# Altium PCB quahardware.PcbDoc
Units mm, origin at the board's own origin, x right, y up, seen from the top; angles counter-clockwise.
Board outline 80 x 75 mm, 2 copper layers (Top Layer, Bottom Layer); 57 components, 46 nets, 248 pads, 42 vias.
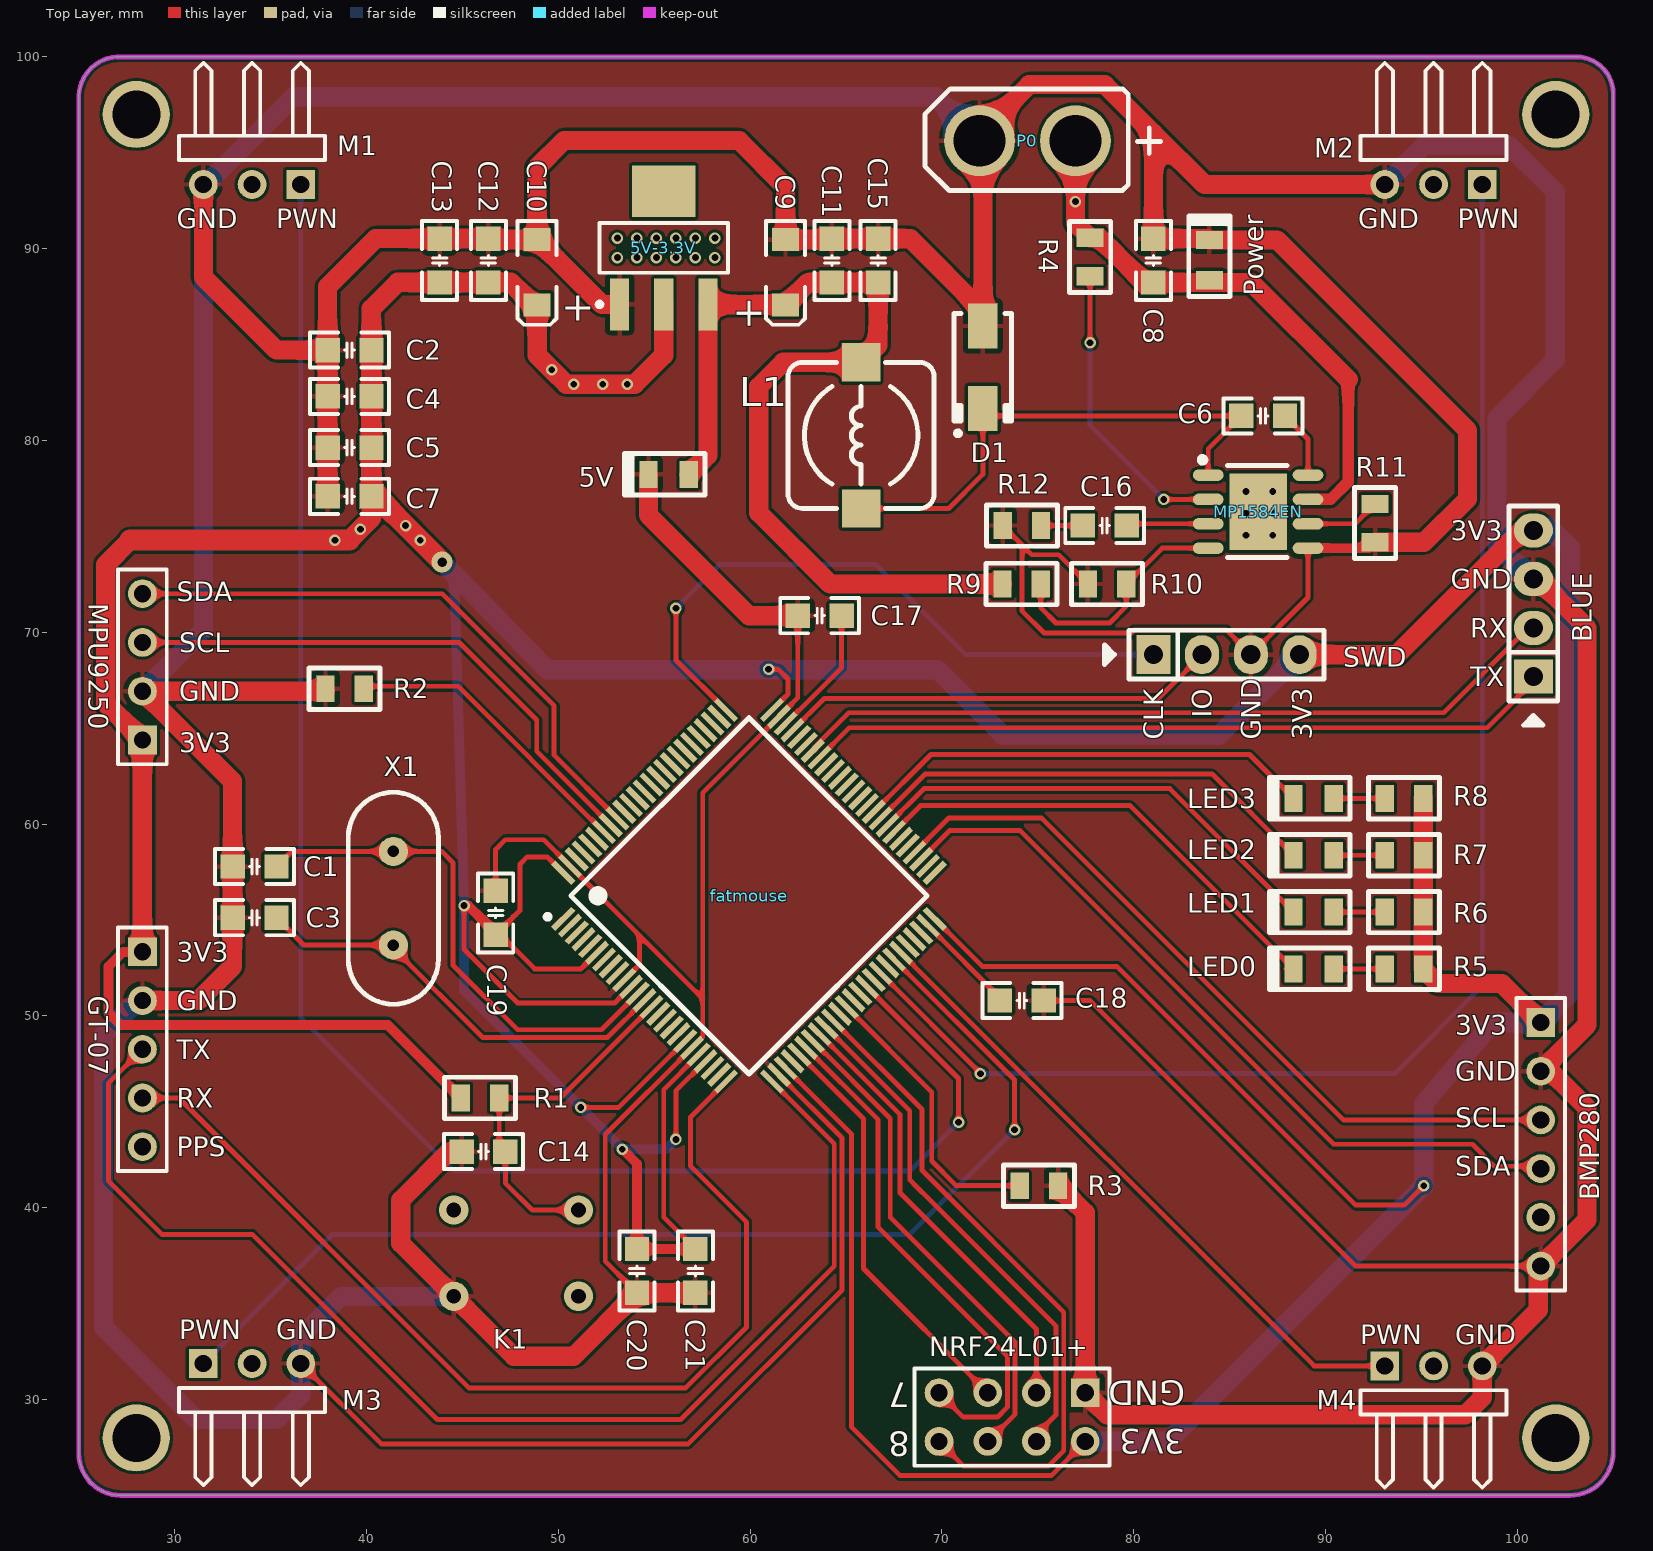
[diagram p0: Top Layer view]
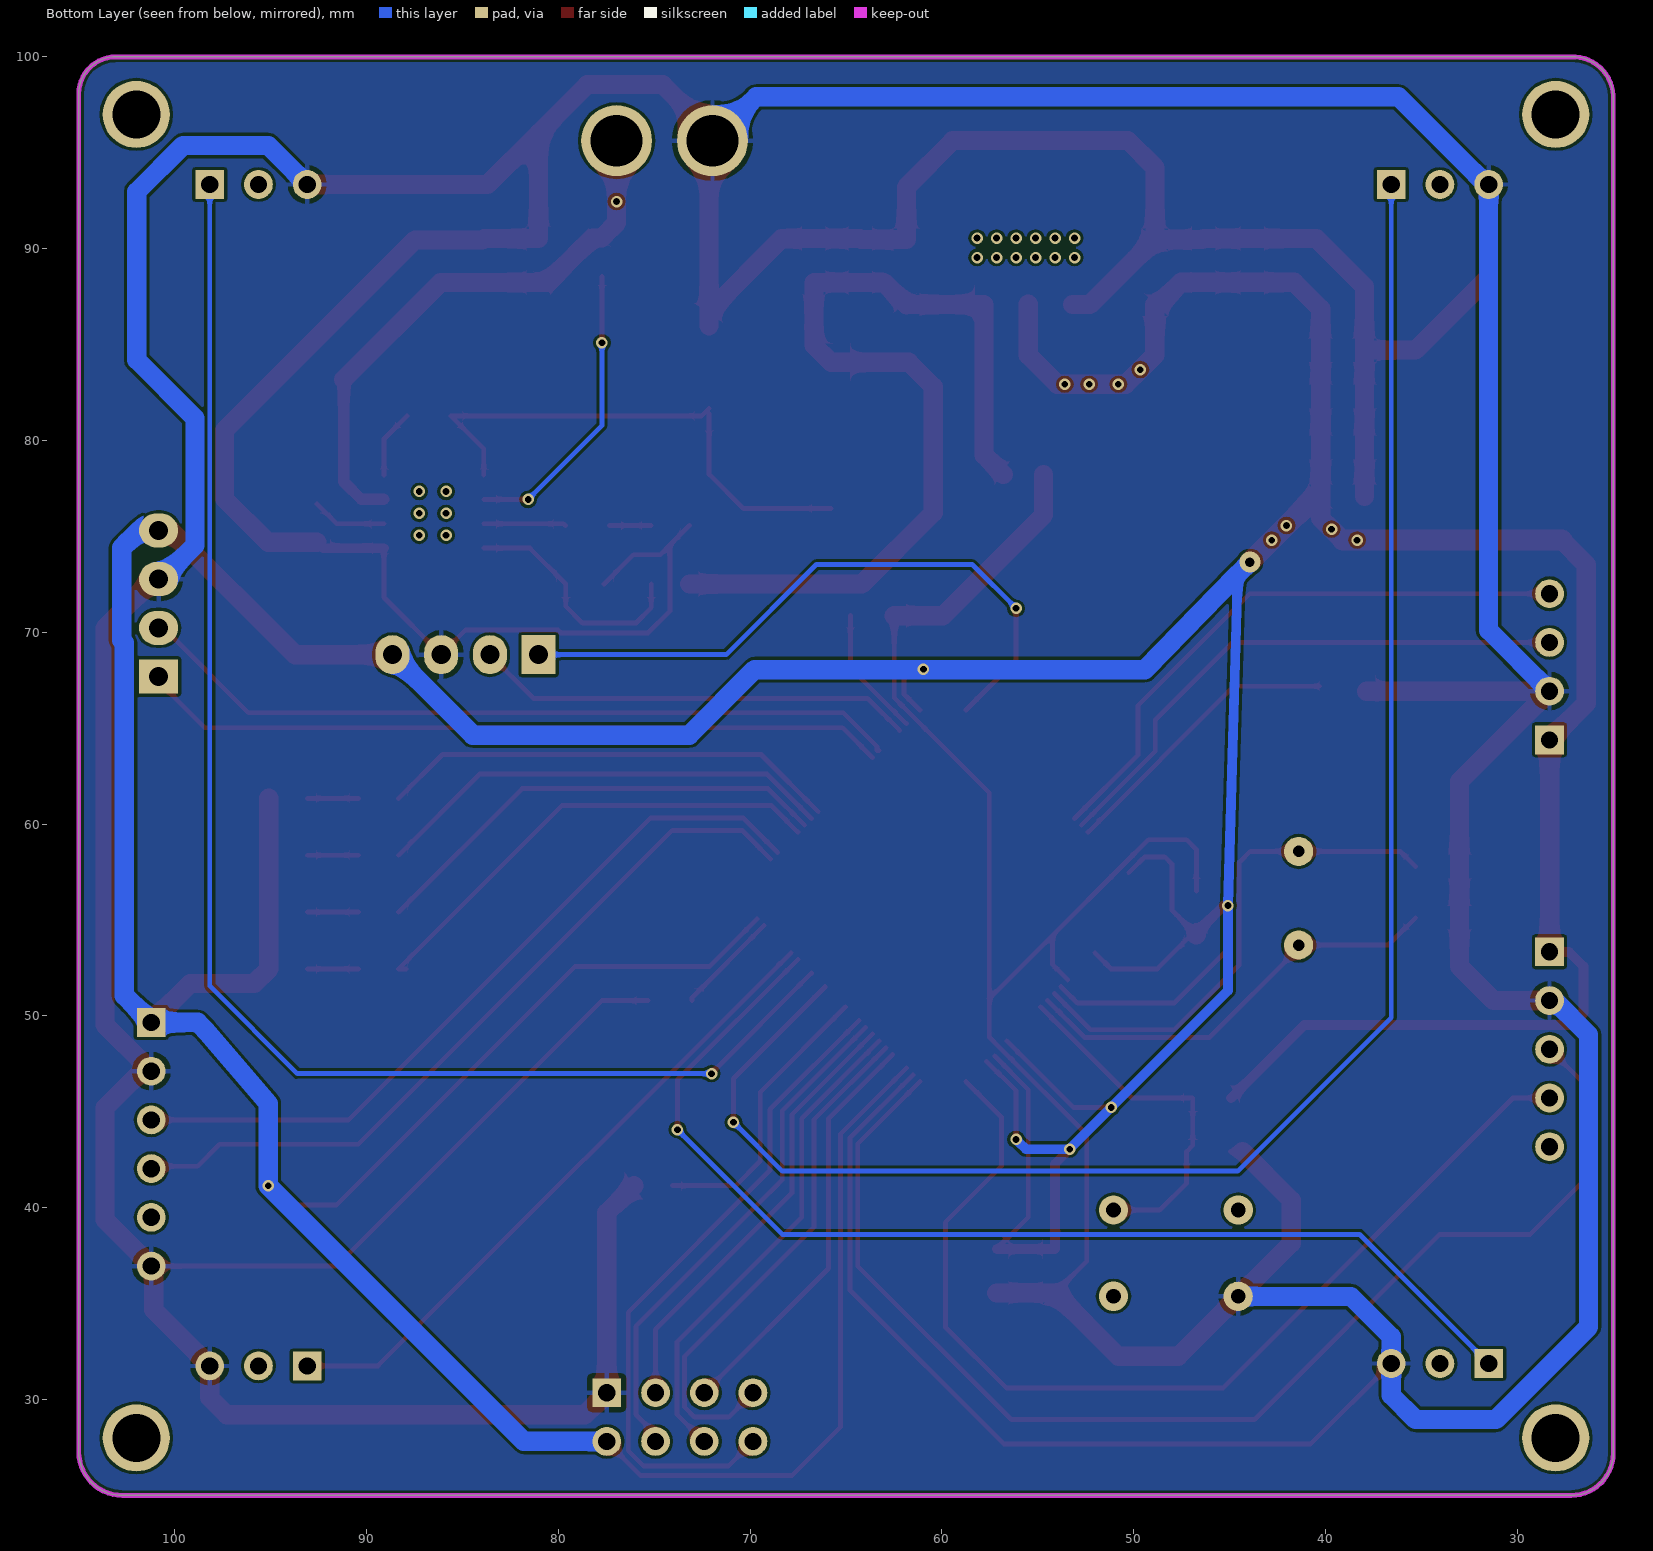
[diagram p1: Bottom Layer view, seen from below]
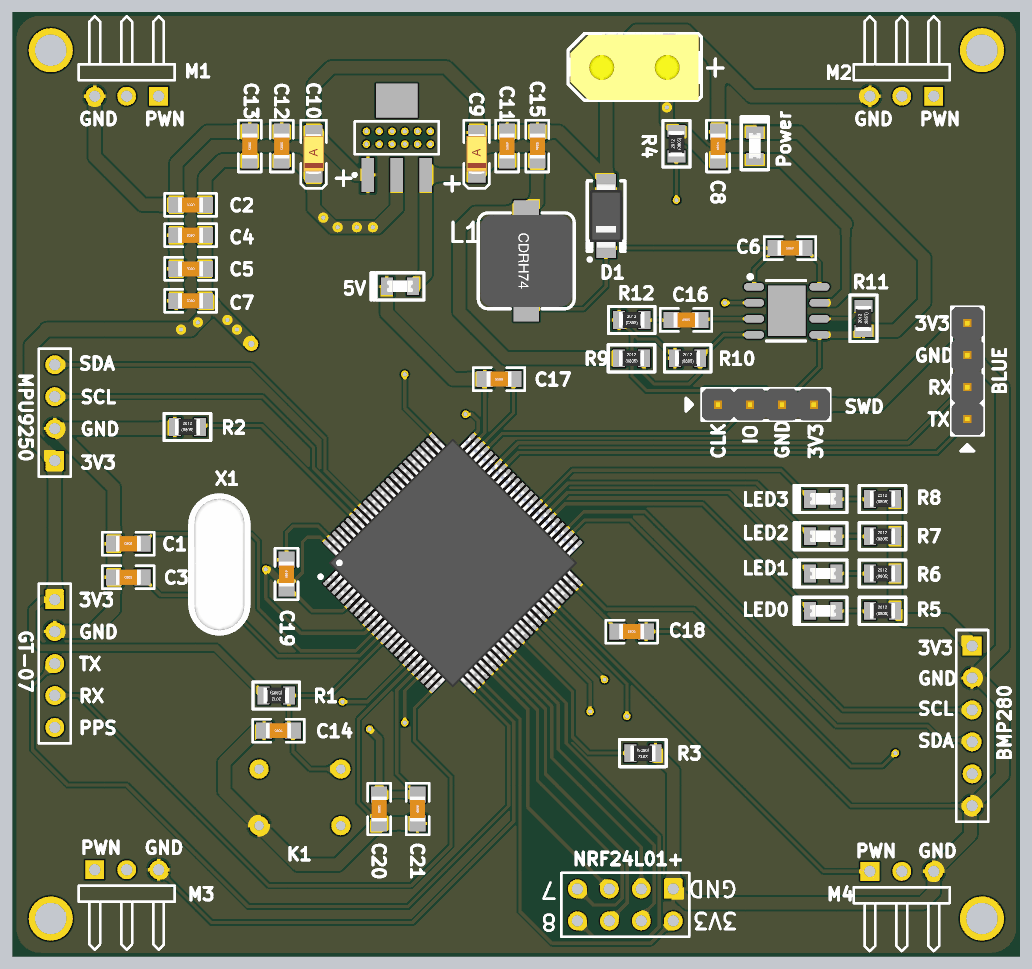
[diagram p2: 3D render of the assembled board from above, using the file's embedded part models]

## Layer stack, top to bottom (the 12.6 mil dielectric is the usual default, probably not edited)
Top Solder: solder mask 0.0102, Solder Resist, Dk 3.5
Top Layer: signal copper 0.0356
Dielectric 1: dielectric 0.32, FR-4, Dk 4.8
Bottom Layer: signal copper 0.0356
Bottom Solder: solder mask 0.0102, Solder Resist, Dk 3.5

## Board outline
25,27.197 25,97.981 cw(c27.126,97.882) 26.975,100.004 26.975,100 103.073,100 cw(c103.073,98.073) 105,98.073 105,27.276 cw(c102.724,27.276) 102.724,25 27.197,25 cw(c27.197,27.197)

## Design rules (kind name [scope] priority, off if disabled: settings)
Clearance [All] p1: gap=0.147 ignorepadtopadclearanceinfootprint=FALSE
PolygonConnect [All] p1: connectstyle=Relief reliefconductorwidth=0.254 reliefentries=4 polygonreliefangle="90 Angle" airgapwidth=0.254
RoutingVias [All] p1: holewidth=0.711 width=1.27 viastyle="Through Hole" minholewidth=0.711 minwidth=1.27 maxholewidth=0.711 maxwidth=1.27
SolderMaskExpansion [All] p1: expansion=0.102
Width [InNet('3.3V')] p1: maxlimit=2.54 minlimit=0.254 preferedwidth=1.016
30 further rules are at their usual default settings.

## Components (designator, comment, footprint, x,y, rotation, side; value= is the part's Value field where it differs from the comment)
5V "BLUE" LED-0805 55.753,78.232 r180 top (schematic designator LED6)
5V-3.3V "LM1117-3.3" SOT223_M 55.499,90.043 r90 top
BLUE "Header 4" PIN-4-2.54-1.0 100.838,71.501 r90 top
BMP280 "Header 6" HDR1X6 101.219,49.657 r270 top
C1 "Cap" "C 0805" 34.163,57.785 r0 top value=22pF
C2 "Cap" "C 0805" 39.116,84.709 r180 top value=100pF
C3 "Cap" "C 0805" 34.163,55.118 r0 top value=22pF
C4 "Cap" "C 0805" 39.116,82.296 r180 top value=100pF
C5 "Cap" "C 0805" 39.116,79.629 r180 top value=100pF
C6 "Cap" "C 0805" 86.741,81.28 r180 top value=100nF
C7 "Cap" "C 0805" 39.116,77.089 r180 top value=100pF
C8 "Cap" "C 0805" 81.026,89.381 r90 top value=10uF
C9 "10uF" "CD A(3216)" 61.849,88.773 r90 top
C10 "10uF" "CD A(3216)" 48.895,88.773 r90 top
C11 "0.01uF" "C 0805" 64.262,89.381 r270 top
C12 "0.01uF" "C 0805" 46.355,89.381 r270 top
C13 "0.01uF" "C 0805" 43.815,89.381 r270 top
C14 "Cap" "C 0805" 46.101,42.926 r0 top value=100pF
C15 "Cap" "C 0805" 66.675,89.381 r90 top value=22uF
C16 "Cap" "C 0805" 78.486,75.565 r0 top value=150pF
C17 "Cap" "C 0805" 63.627,70.866 r180 top value=2.2uF
C18 "Cap" "C 0805" 74.168,50.8 r0 top value=2.2uF
C19 "Cap" "C 0805" 46.736,55.372 r90 top value=100nF
C20 "Cap" "C 0805" 54.102,36.703 r90 top value=1uF
C21 "Cap" "C 0805" 57.15,36.703 r90 top value=100nF
D1 "D Schottky" SMA 72.136,83.82 r270 top
fatmouse "STM32F407VET6" QFP-100-0.5 59.944,56.261 r45 top
GT-07 "Header 5" HDR1X5 28.321,53.34 r270 top
K1 "KEY_L" key 51.054,39.878 r180 top (schematic designator KEY1)
L1 "Inductor" CDRH74 65.786,80.264 r90 top value=4.7uH
LED0 "BLUE" LED-0805 89.374,52.451 r180 top
LED1 "BLUE" LED-0805 89.374,55.414 r180 top
LED2 "BLUE" LED-0805 89.374,58.378 r180 top
LED3 "BLUE" LED-0805 89.374,61.341 r180 top
M1 "Header 3H" HDR1X3H 36.576,93.345 r180 top (schematic designator MOTOR1)
M2 "Header 3H" HDR1X3H 98.171,93.345 r180 top (schematic designator MOTOR2)
M3 "Header 3H" HDR1X3H 31.496,31.877 r0 top (schematic designator MOTOR3)
M4 "Header 3H" HDR1X3H 93.091,31.75 r0 top (schematic designator MOTOR4)
MP1584EN "MP1584EN" LC-SOIC-8_EP_150mil 86.487,76.29 r270 top
MPU9250 "Header 4" HDR1X4 28.321,64.389 r90 top
NRF24L01+ "Header 4X2" HDR2X4 77.47,30.353 r180 top
P0 "Header 2" xt30 76.962,95.631 r180 top
Power "BLUE" LED-0805 83.947,89.408 r90 top (schematic designator LED5)
R1 "Res1" 0805 45.919,45.72 r180 top value=1K
R2 "Res1" 0805 38.862,67.056 r0 top value=1K
R3 "Res1" 0805 75.057,41.148 r180 top value=1K
R4 "Res1" 0805 77.724,89.563 r90 top value=100K
R5 "Res1" 0805 94.091,52.451 r0 top value=1K
R6 "Res1" 0805 94.091,55.414 r0 top value=1K
R7 "Res1" 0805 94.091,58.378 r0 top value=1K
R8 "Res1" 0805 94.091,61.341 r0 top value=1K
R9 "Res1" 0805 74.152,72.517 r0 top value=201K
R10 "Res1" 0805 78.613,72.517 r0 top value=40.2K
R11 "Res1" 0805 92.583,75.692 r90 top value=100K
R12 "Res1" 0805 74.168,75.565 r0 top value=100K
SWD "Header 4" PIN-4-2.54-1.0 84.836,68.834 r0 top
X1 "8MHz" HC49S 41.402,56.134 r270 top

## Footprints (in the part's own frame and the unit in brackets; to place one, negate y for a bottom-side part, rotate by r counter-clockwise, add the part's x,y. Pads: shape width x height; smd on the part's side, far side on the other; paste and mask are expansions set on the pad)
0805 [mm] "SMD, 0805"
  rect 0.95x1.4 smd: 1(-1,0) 2(1,0)
  silkscreen extent -1.85,-1.08 1.85,1.08, body extent -1,-0.62 1,0.63, height 0.45
"C 0805" [mil] "无极性贴片电容"
  rect 50x50 smd: 1(-45,0) 2(45,0)
  silkscreen extent -81,-36 81,36, body extent -39,-24 39,24, height 20
"CD A(3216)" [mm] "长3.2mm，宽1.6mm，厚1.6mm"
  rect 1.2x1.4 smd: 1(-1.7,0) 2(1.7,0)
  silkscreen extent -2.74,-1.02 2.67,1.02, body extent -1.6,-0.8 1.6,0.8, height 1.6
CDRH74 [mm] "7.3*7.3*4.5mm（长宽高）"
  rect 2x2 smd: 1(-3.81,0) 2(3.81,0)
  silkscreen extent -3.81,-3.81 3.81,3.81, body extent -3.65,-3.65 3.65,3.65, height 4.5
HC49S [mm] "CRYSTAL"
  round 1.524 hole 0.6: 1(-2.44,0) 2(2.44,0)
  silkscreen extent -5.52,-2.35 5.52,2.35, body extent -5.49,-2.24 5.49,2.25, height 3.6
HDR1X3H [mm] "Connector; Header; 3 Position; Right Angle"
  rect 1.5x1.5 hole 0.9: 1(0,0)
  round 1.5 hole 0.9: 2(2.54,0) 3(5.08,0)
  silkscreen extent -1.27,-6.35 6.35,-1.27
HDR1X4 [mm] "Connector; Header; 4 Position"
  rect 1.5x1.5 hole 0.9: 1(0,0)
  round 1.5 hole 0.9: 2(2.54,0) 3(5.08,0) 4(7.62,0)
  silkscreen extent -1.27,-1.27 8.89,1.27
HDR1X5 [mm] "Connector; Header; 5 Position"
  rect 1.5x1.5 hole 0.9: 1(0,0)
  round 1.5 hole 0.9: 2(2.54,0) 3(5.08,0) 4(7.62,0) 5(10.16,0)
  silkscreen extent -1.27,-1.27 11.43,1.27
HDR1X6 [mm] "Connector; Header; 6 Position"
  rect 1.5x1.5 hole 0.9: 1(0,0)
  round 1.5 hole 0.9: 2(2.54,0) 3(5.08,0) 4(7.62,0) 5(10.16,0) 6(12.7,0)
  silkscreen extent -1.27,-1.27 13.97,1.27
HDR2X4 [mm] "Connector; Header; 4x2 Position"
  rect 1.5x1.5 hole 0.9: 1(0,0)
  round 1.5 hole 0.9: 2(0,2.54) 3(2.54,0) 4(2.54,2.54) 5(5.08,0) 6(5.08,2.54) 7(7.62,0) 8(7.62,2.54)
  silkscreen extent -1.27,-1.27 8.89,3.81
key [mil]
  round 60 hole 30: 1(255.91,177.17) 2(0,0)
LC-SOIC-8_EP_150mil [mm]
  rect 4x3 smd: 0(0,0)
  oval 0.6x1.6 smd: 1(-1.905,-2.6) 2(-0.635,-2.6) 3(0.635,-2.6) 4(1.905,-2.6) 5(1.905,2.6) 6(0.635,2.6) 7(-0.635,2.6) 8(-1.905,2.6)
  silkscreen extent -2.85,-3.05 2.4,1.5
LED-0805 [mm] "LED, SMD, 0805"
  rect 0.95x1.4 smd: 1(-1.05,0) 2(1.05,0)
  silkscreen extent -1.9,-1.08 2.3,1.08, body extent -1.03,-0.46 1.03,0.45, height 0.85
PIN-4-2.54-1.0 [mil] "Pin Header"
  rect 70x80 hole 39.37: 1(-150,0)
  oval 70x80 hole 39.37: 2(-50,0) 3(50,0) 4(150,0)
  silkscreen extent -250,-50 200,50, body extent -200,-50 200,50, height 398
QFP-100-0.5 [mm] "QFP-100"
  rect 1.5x0.3 smd: 1(-7.7,6) 2(-7.7,5.5) 3(-7.7,5) 4(-7.7,4.5) 5(-7.7,4) 6(-7.7,3.5) 7(-7.7,3) 8(-7.7,2.5) 9(-7.7,2) 10(-7.7,1.5) 11(-7.7,1) 12(-7.7,0.5) 13(-7.7,0) 14(-7.7,-0.5) 15(-7.7,-1) 16(-7.7,-1.5) 17(-7.7,-2) 18(-7.7,-2.5) 19(-7.7,-3) 20(-7.7,-3.5) 21(-7.7,-4) 22(-7.7,-4.5) 23(-7.7,-5) 24(-7.7,-5.5) 25(-7.7,-6) 51(7.7,-6) 52(7.7,-5.5) 53(7.7,-5) 54(7.7,-4.5) 55(7.7,-4) 56(7.7,-3.5) 57(7.7,-3) 58(7.7,-2.5) 59(7.7,-2) 60(7.7,-1.5) 61(7.7,-1) 62(7.7,-0.5) 63(7.7,0) 64(7.7,0.5) 65(7.7,1) 66(7.7,1.5) 67(7.7,2) 68(7.7,2.5) 69(7.7,3) 70(7.7,3.5) 71(7.7,4) 72(7.7,4.5) 73(7.7,5) 74(7.7,5.5) 75(7.7,6)
  rect 0.3x1.5 smd: 26(-6,-7.7) 27(-5.5,-7.7) 28(-5,-7.7) 29(-4.5,-7.7) 30(-4,-7.7) 31(-3.5,-7.7) 32(-3,-7.7) 33(-2.5,-7.7) 34(-2,-7.7) 35(-1.5,-7.7) 36(-1,-7.7) 37(-0.5,-7.7) 38(0,-7.7) 39(0.5,-7.7) 40(1,-7.7) 41(1.5,-7.7) 42(2,-7.7) 43(2.5,-7.7) 44(3,-7.7) 45(3.5,-7.7) 46(4,-7.7) 47(4.5,-7.7) 48(5,-7.7) 49(5.5,-7.7) 50(6,-7.7) 76(6,7.7) 77(5.5,7.7) 78(5,7.7) 79(4.5,7.7) 80(4,7.7) 81(3.5,7.7) 82(3,7.7) 83(2.5,7.7) 84(2,7.7) 85(1.5,7.7) 86(1,7.7) 87(0.5,7.7) 88(0,7.7) 89(-0.5,7.7) 90(-1,7.7) 91(-1.5,7.7) 92(-2,7.7) 93(-2.5,7.7) 94(-3,7.7) 95(-3.5,7.7) 96(-4,7.7) 97(-4.5,7.7) 98(-5,7.7) 99(-5.5,7.7) 100(-6,7.7)
  silkscreen extent -8.33,-6.57 6.57,6.78, body extent -8.02,-8.02 8.01,8.01, height 1.6
SMA [mm] "DO-214AC"
  rect 2.35x1.55 smd: 1(-2.15,0) 2(2.15,0)
  silkscreen extent -2.8,-1.5 3.58,1.5, body extent -2.6,-1.3 2.6,1.3, height 2.64
SOT223_M [mm] "SOT223, 4-Leads, Body 6.5x3.5mm, Pitch 2.3mm, Lead Span 7mm, IPC Low Density"
  rect 2.7x1 smd: 1(-2.95,2.3) 2(-2.95,0) 3(-2.95,-2.3)
  rect 2.7x3.3 smd: 4(2.95,0)
  silkscreen extent -3.07,-3.35 1.3,3.47, body extent -1.85,-3.35 1.85,3.35, height 1.7
xt30 [mm]
  round 3.7 hole 2.7: 1(0,0) 2(5,0)
  silkscreen extent -4.45,-2.7 7.85,2.6, body extent -2.62,-2.7 7.78,2.6, height 12.6

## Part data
5V LED0 LED1 LED2 LED3 Power: library part LED
BLUE MPU9250 SWD: "Header, 4-Pin"
BMP280: "Header, 6-Pin"
C1 C2 C3 C4 C5 C6 C7 C8 C14 C15 C16 C17 C18 C19 C20 C21: "Capacitor"
C9 C10: library part CAP
C11 C12 C13: library part C
D1: "Schottky Diode"
GT-07: "Header, 5-Pin"
K1: library part KEY
M1 M2 M3 M4: "Header, 3-Pin, Right Angle"
NRF24L01+: "Header, 4-Pin, Dual row"
P0: "Header, 2-Pin"
R1 R2 R3 R4 R5 R6 R7 R8 R9 R10 R11 R12: "Resistor"
X1: library part XTAL-2, "Crystal"

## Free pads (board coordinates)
  round 3.5 hole 2.5: 0(28,28) 0(28,97) 0(102,28) 0(102,97)

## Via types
v1: diameter 0.6, hole 0.35, Top Layer to Bottom Layer, 39 vias
v2: diameter 1.524, hole 0.762, Top Layer to Bottom Layer, 2 vias
v3: diameter 1.1, hole 0.5, Top Layer to Bottom Layer, 1 vias

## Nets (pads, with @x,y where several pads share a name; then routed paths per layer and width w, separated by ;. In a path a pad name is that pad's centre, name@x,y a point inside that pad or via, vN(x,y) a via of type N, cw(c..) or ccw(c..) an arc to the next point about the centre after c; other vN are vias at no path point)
3.3V: 5V-3.3V.2 BLUE.4 BMP280.1 C2.1 C4.1 C5.1 C7.1 C10.1 C12.2 C13.2 C19.1 C20.2 C21.2 fatmouse.6 fatmouse.11 fatmouse.19 fatmouse.21 fatmouse.22 fatmouse.28 fatmouse.50 fatmouse.75 fatmouse.100 GT-07.1 MPU9250.1 NRF24L01+.2 R1.2 R5.2 R6.2 R7.2 R8.2 SWD.4 | length 409
  Top Layer w0.254: v1(45.085,55.753) 45.085,53.467 47.879,50.673 52.942,50.673 fatmouse.11 ; C19.1 48.006,55.499 48.006,57.912 48.387,58.293 49.427,58.293 fatmouse.100 ; C19.1@46.99,54.229 48.768,52.451 51.184,52.451 fatmouse.6 ; v1(51.178,45.227) 53.152,45.227 fatmouse.19 ; v1(56.134,43.561) 56.134,46.087 fatmouse.22 ; C21.2 55.499,39.497 55.499,46.159 fatmouse.21@57.248,47.908 ; v1(60.96,68.072) 61.468,68.072 61.976,67.564 61.976,66.778 fatmouse.75 ; fatmouse.28 65.278,43.856 65.278,28.575 67.818,26.035 75.692,26.035 NRF24L01+.2 ; fatmouse.50 72.112,52.578 79.121,52.578 91.567,40.132 94.107,40.132 v1(95.123,41.148)
  Top Layer w0.5: 26.543,52.578 27.305,53.34 GT-07.1 ; v1(45.085,55.753) 45.302,55.753 C19.1@46.736,54.319 ; v1(53.34,43.053) 54.102,42.291 C20.2 C21.2
  Top Layer w0.524: 26.543,52.578 26.543,50.165 27.178,49.53 41.109,49.53 R1.2
  Top Layer w1.016: 27.686,74.803 26.416,73.533 26.416,66.294 MPU9250.1 GT-07.1 ; 39.116,74.803 v1(39.688,75.374) 40.259,75.946 C7.1 ; C7.1@40.513,77.089 C7.1 ; C19.1 C19.1@46.736,54.319 ; 5V-3.3V.2 55.499,84.455 53.975,82.931 v1(53.594,82.931) v1(52.324,82.931) v1(50.8,82.931) 50.419,82.931 v1(49.657,83.693) 48.895,84.455 C10.1 48.69,87.073 47.525,88.238 C12.2 C13.2 41.629,88.238 40.259,86.868 C2.1 C4.1 C5.1 C7.1 ; SWD.4 93.726,68.834 100.203,75.311 BLUE.4 BLUE.4@101.092,75.311 ; R8.2 R7.2 R6.2 R5.2 95.853,51.689 99.187,51.689 BMP280.1
  Top Layer w1.1: 27.686,74.803 v1(38.354,74.803) 39.116,74.803 ; C7.1@40.513,77.089 v1(42.037,75.565) v1(42.799,74.803) v3(43.942,73.66)
  Bottom Layer w0.5: 44.577,73.025 v1(45.085,55.753) 45.085,51.32 v1(51.178,45.227) 51.178,45.215 v1(53.34,43.053) 55.626,43.053 v1@56.007,43.434
  Bottom Layer w1.016: v3(43.942,73.66) 44.577,73.025 49.423,68.052 69.763,68.052 73.172,64.643 84.455,64.643 SWD.4 ; NRF24L01+.2 81.788,27.813 v1(95.123,41.148) 95.123,45.424 98.425,49.276 98.806,49.657 BMP280.1 102.616,51.054 102.616,69.444 102.763,69.591 102.763,74.402 101.854,75.311 BLUE.4@101.092,75.311
5V: 5V-3.3V.3 5V.1 C9.1 C11.2 C15.1 L1.2 R9.1 | length 49.8
  Top Layer w0.254: C9.1@61.829,87.093 C9.1
  Top Layer w1: 5V.1 57.799,79.228 5V-3.3V.3 C9.1@61.829,87.093 ; C9.1 63.014,88.238 C11.2 C15.1 66.675,84.963 L1.2 61.722,84.074 60.452,82.804 60.452,76.234 64.169,72.517 R9.1
BLUE_RX: BLUE.2 fatmouse.69 | length 40.6
  Top Layer w0.254: fatmouse.69 63.375,63.827 63.375,64.042 65.139,65.806 96.159,65.806 100.584,70.231 BLUE.2 BLUE.2@101.092,70.231
BLUE_TX: BLUE.1 fatmouse.68 | length 39.2
  Top Layer w0.254: fatmouse.68 65.171,65.024 98.425,65.024 BLUE.1@101.092,67.691
BMP_SCL: BMP280.3 fatmouse.54 | length 39.8
  Top Layer w0.254: fatmouse.54 70.372,60.325 75.184,60.325 90.932,44.577 BMP280.3@101.092,44.577
BMP_SDA: BMP280.4 fatmouse.53 | length 40
  Top Layer w0.254: fatmouse.53 70.424,59.67 74.061,59.67 90.424,43.307 97.663,43.307 98.806,42.164 BMP280.4@101.092,42.164
BOOT0: fatmouse.94 R2.2 | length 15.2
  Top Layer w0.254: R2.2@40.315,67.183 44.779,67.183 fatmouse.94
BOOT1: fatmouse.37 R3.2 | length 15
  Top Layer w0.254: fatmouse.37 69.469,46.029 69.469,42.434 70.755,41.148 R3.2
BST: C6.1 MP1584EN.8 | length 3.6
  Top Layer w0.254: C6.1 89.087,80.077 MP1584EN.8
CH1: fatmouse.40 M1.1 | length 91
  Top Layer w0.254: fatmouse.40 66.096,51.506 70.866,46.736 v1(70.866,44.45)
  Bottom Layer w0.254: M1.1@36.576,93.218 36.576,49.911 44.577,41.91 68.326,41.91 v1(70.866,44.45)
CH2: fatmouse.42 M2.1 | length 77.3
  Top Layer w0.254: fatmouse.42@66.803,52.196 fatmouse.42 72.009,47.024 v1(72.009,46.99)
  Bottom Layer w0.254: v1(72.009,46.99) 93.599,46.99 98.171,51.562 M2.1
CH3: fatmouse.44 M3.1 | length 58.8
  Top Layer w0.254: fatmouse.44 73.787,46.661 v1(73.787,44.069)
  Bottom Layer w0.254: M3.1 38.227,38.608 68.326,38.608 v1(73.787,44.069)
CH4: fatmouse.45 M4.1 | length 34.2
  Top Layer w0.254: fatmouse.45 89.405,31.75 M4.1
COMP: C16.2 MP1584EN.3 | length 4.3
  Top Layer w0.254: C16.2 79.719,75.655 MP1584EN.3
EN: MP1584EN.2 R4.1 | length 15.5
  Top Layer w0.254: v1(77.724,85.09) R4.1 ; v1(81.571,76.925) MP1584EN.2
  Bottom Layer w0.254: v1(77.724,85.09) 77.724,80.772 v1(81.571,76.925)
FB: MP1584EN.4 R9.2 R10.2 | length 12.6
  Top Layer w0.254: R9.2 75.152,71.279 75.946,70.485 78.74,70.485 79.613,71.358 R10.2 81.481,74.385 MP1584EN.4
FREQ: MP1584EN.6 R11.2 | length 3.9
  Top Layer w0.254: MP1584EN.6 91.546,75.655 R11.2
GND: 5V-3.3V.1 5V.2 BLUE.3 BMP280.2 BMP280.6 C1.1 C2.2 C3.1 C4.2 C5.2 C7.2 C8.2 C9.2 C10.2 C11.1 C12.1 C13.1 C14.1 C15.2 C17.2 C18.2 C19.2 C20.1 C21.1 D1.1 fatmouse.10 fatmouse.20 fatmouse.27 fatmouse.74 fatmouse.99 GT-07.2 K1.1 M1.3 M2.3 M3.3 M4.3 MP1584EN.5 MPU9250.2 NRF24L01+.1 P0.2 Power.2 R2.1 R3.1 R10.1 R11.1 R12.1 SWD.3 | length 610.1
  Top Layer w0.254: M3.3 40.767,27.686 56.769,27.686 64.79,35.707 64.79,43.637 fatmouse.27 ; R2.1@37.862,66.929 R2.1@37.973,66.929 ; C14.1@44.323,42.926 C14.1 ; C12.1 C12.1@46.406,90.473 ; C19.2 46.736,58.674 47.244,59.182 49.245,59.182 fatmouse.99 54.229,54.198 ; fatmouse.10 54.229,52.667 54.229,54.198 ; C20.1 52.451,37.211 52.451,43.818 fatmouse.20 57.531,48.898 57.531,50.896 ; C17.2 62.484,66.579 fatmouse.74 57.531,61.626 57.531,50.896 ; C11.1@64.211,90.473 C11.1 ; P0.2 P0.2@71.962,95.965 ; R12.1 74.184,74.549 ; C18.2 77.724,50.8 91.567,36.957 BMP280.6@101.092,36.957 ; R10.1 76.089,74.041 74.692,74.041 74.184,74.549 ; Power.2@83.881,90.524 Power.2 ; MP1584EN.5 89.087,71.815 SWD.3 84.816,70.124 80.024,70.124 79.861,69.961 75.327,69.961 74.184,71.104 74.184,74.549 ; R11.1@92.276,74.385 R11.1 ; 54.229,54.198 57.531,50.896
  Top Layer w0.5: MP1584EN.5 R11.1@92.276,74.385
  Top Layer w1: GT-07.2 31.242,50.8 33.02,52.578 C3.1 C1.1 33.02,62.23 MPU9250.2 R2.1@37.862,66.929 ; M1.3@31.496,93.218 31.496,88.519 35.306,84.709 C2.2 ; C7.2 C5.2 C4.2 C2.2 ; C14.1@44.323,42.926 41.783,40.386 41.783,38.149 K1.1 47.674,32.258 50.8,32.258 C20.1 C21.1 ; C12.1 C13.1 40.486,90.524 37.973,88.011 C2.2 ; C12.1@46.406,90.473 C10.2 ; 5V-3.3V.1 52.275,87.093 C10.2 ; 5V.2 54.703,76.107 59.944,70.866 C17.2 ; C11.1@64.211,90.473 C9.2 61.849,93.218 59.436,95.631 50.292,95.631 48.895,94.234 C10.2 ; C11.1 C15.2 68.353,90.524 D1.1@72.136,86.741 ; P0.2 72.136,95.457 D1.1@72.136,86.741 ; P0.2@71.962,95.965 74.549,98.552 78.486,98.552 81.026,96.012 ; D1.1 D1.1@72.136,86.741 ; R3.1 77.47,39.735 NRF24L01+.1 78.613,29.21 97.282,29.21 98.171,30.099 M4.3 101.092,34.671 BMP280.6@101.092,36.957 ; Power.2@83.881,90.524 C8.2 81.026,96.012 ; Power.2 87.469,90.458 97.409,80.518 97.409,76.962 95.139,74.692 R11.1 ; M2.3 83.693,93.345 81.026,96.012 ; BLUE.3@101.092,72.771 103.632,70.231 103.632,49.53 101.473,47.371 103.632,45.212 103.632,39.37 BMP280.6
  Bottom Layer w0.254: GT-07.2@28.067,50.8 GT-07.2 ; BLUE.3@100.711,72.771 BLUE.3 BLUE.3@101.092,72.771
  Bottom Layer w1: GT-07.2@28.067,50.8 26.289,49.022 26.289,33.782 31.115,28.956 35.306,28.956 36.576,30.226 M3.3 36.576,33.274 38.68,35.378 K1.1 ; MPU9250.2 31.496,70.104 31.496,93.218 36.195,97.917 69.676,97.917 P0.2 ; M2.3 95.123,95.377 99.568,95.377 101.981,92.964 101.981,84.201 98.945,81.165 98.945,74.537 BLUE.3@100.711,72.771
GT_RXD: fatmouse.25 GT-07.4 | length 53.8
  Top Layer w0.254: GT-07.4 30.226,45.72 45.339,30.607 56.642,30.607 59.817,33.782 59.817,39.243 56.896,42.164 56.896,44.728 fatmouse.25
GT_TXD: fatmouse.26 GT-07.3 | length 64.9
  Top Layer w0.254: GT-07.3 26.543,46.482 26.543,41.402 29.337,38.608 34.036,38.608 43.688,28.956 56.388,28.956 64.389,36.957 64.389,43.331 fatmouse.26
IMU_SCL: fatmouse.93 MPU9250.3 | length 29.3
  Top Layer w0.254: MPU9250.3 44.831,69.469 48.875,65.425 48.875,63.794 fatmouse.93
IMU_SDA: fatmouse.92 MPU9250.4 | length 31.1
  Top Layer w0.254: MPU9250.4 43.942,72.009 49.784,66.167 49.784,63.593 fatmouse.92
LED0: fatmouse.57 LED0.2 | length 25.3
  Top Layer w0.254: fatmouse.57 68.886,60.96 79.815,60.96 LED0.2 LED0.2@87.936,52.451
LED1: fatmouse.58 LED1.2 | length 24.6
  Top Layer w0.254: fatmouse.58 69.068,61.849 81.889,61.849 LED1.2
LED2: fatmouse.59 LED2.2 | length 24.2
  Top Layer w0.254: fatmouse.59 69.122,62.611 84.091,62.611 LED2.2
LED3: fatmouse.60 LED3.2 | length 24.1
  Top Layer w0.254: fatmouse.60 69.431,63.627 86.038,63.627 LED3.2
NetC16_1: C16.1 R12.2 | length 2.2
  Top Layer w0.254: R12.2 C16.1
NetLED0_1: LED0.1 R5.1 | length 2.7
  Top Layer w0.254: LED0.1 R5.1
NetLED1_1: LED1.1 R6.1 | length 2.7
  Top Layer w0.254: LED1.1 R6.1
NetLED2_1: LED2.1 R7.1 | length 2.7
  Top Layer w0.254: LED2.1 R7.1
NetLED3_1: LED3.1 R8.1 | length 2.7
  Top Layer w0.254: LED3.1 R8.1
NRF_CE: fatmouse.33 NRF24L01+.3 | length 23.4
  Top Layer w0.254: fatmouse.33 67.818,44.851 67.818,40.767 74.93,33.655 NRF24L01+.3
NRF_CSN: fatmouse.34 NRF24L01+.4 | length 27.1
  Top Layer w0.254: fatmouse.34 68.326,45.051 68.326,41.447 68.7,41.074 69.313,40.461 69.619,40.154 75.954,33.819 75.954,29.218 74.739,28.003 NRF24L01+.4
NRF_IRQ: fatmouse.35 NRF24L01+.8 | length 34.8
  Top Layer w0.254: fatmouse.35 68.961,45.123 68.961,41.947 76.355,34.553 76.355,27.333 75.565,26.543 71.12,26.543 NRF24L01+.8
NRF_MISO: fatmouse.31 NRF24L01+.7 | length 27.4
  Top Layer w0.254: fatmouse.31 66.675,44.58 66.675,38.989 73.414,32.25 73.414,29.599 72.898,29.083 71.12,29.083 NRF24L01+.7
NRF_MOSI: fatmouse.32 NRF24L01+.6 | length 25.8
  Top Layer w0.254: fatmouse.32 67.31,44.652 67.31,39.497 73.815,32.992 73.815,29.238 NRF24L01+.6
NRF_SCK: fatmouse.30 NRF24L01+.5 | length 21.7
  Top Layer w0.254: fatmouse.30 65.913,44.635 65.913,36.83 NRF24L01+.5
OSC_IN: C1.2 fatmouse.12 X1.1 | length 26.9
  Top Layer w0.254: C1.2 36.095,58.574 X1.1 43.915,58.574 44.511,57.978 44.511,52.644 47.879,49.276 52.252,49.276 fatmouse.12
OSC_OUT: C3.2 fatmouse.13 X1.2 | length 22.7
  Top Layer w0.254: C3.2 36.73,53.694 X1.2 41.402,53.535 46.062,48.875 52.558,48.875 fatmouse.13
RST: C14.2 fatmouse.14 K1.2 R1.1 | length 18.9
  Top Layer w0.254: K1.2 48.641,39.878 47.244,41.275 C14.2 46.919,43.251 R1.1 50.11,45.72 fatmouse.14
SW: C6.2 D1.2 L1.1 MP1584EN.1 | length 27.7
  Top Layer w0.254: L1.1 70.358,76.454 72.136,78.232 D1.2@72.136,81.407 ; D1.2 72.526,81.28 C6.2 83.887,79.569 MP1584EN.1
SWCLK: fatmouse.76 SWD.1 | length 34.2
  Top Layer w0.254: v1(56.134,71.247) 56.134,68.556 fatmouse.76
  Bottom Layer w0.254: v1(56.134,71.247) 58.42,73.533 66.548,73.533 71.247,68.834 SWD.1
SWDIO: fatmouse.72 SWD.2 | length 23
  Top Layer w0.254: fatmouse.72 63.867,66.548 81.28,66.548 SWD.2
VCAP_1: C18.1 fatmouse.49 | length 5.5
  Top Layer w0.254: fatmouse.49 73.025,50.958 C18.1
VCAP_2: C17.1 fatmouse.73 | length 6.8
  Top Layer w0.254: fatmouse.73 64.77,68.158 C17.1
VIN: C8.1 MP1584EN.7 P0.1 Power.1 R4.2 | length 29.8
  Top Layer w0.254: Power.1@83.772,88.238 Power.1@83.947,88.063
  Top Layer w0.6: MP1584EN.7 90.26,76.925 91.186,77.851 91.186,83.185
  Top Layer w1: P0.1 v1(76.962,92.456) 76.962,91.337 R4.2@77.597,90.702 ; R4.2 78.22,90.563 80.545,88.238 C8.1 83.772,88.238 86.133,88.238 91.186,83.185
pads on no net: 5V-3.3V.4 BMP280.5 fatmouse.1 fatmouse.2 fatmouse.3 fatmouse.4 fatmouse.5 fatmouse.7 fatmouse.8 fatmouse.9 fatmouse.15 fatmouse.16 fatmouse.17 fatmouse.18 fatmouse.23 fatmouse.24 fatmouse.29 fatmouse.36 fatmouse.38 fatmouse.39 fatmouse.41 fatmouse.43 fatmouse.46 fatmouse.47 fatmouse.48 fatmouse.51 fatmouse.52 fatmouse.55 fatmouse.56 fatmouse.61 fatmouse.62 fatmouse.63 fatmouse.64 fatmouse.65 fatmouse.66 fatmouse.67 fatmouse.70 fatmouse.71 fatmouse.77 fatmouse.78 fatmouse.79 fatmouse.80 fatmouse.81 fatmouse.82 fatmouse.83 fatmouse.84 fatmouse.85 fatmouse.86 fatmouse.87 fatmouse.88 fatmouse.89 fatmouse.90 fatmouse.91 fatmouse.95 fatmouse.96 fatmouse.97 fatmouse.98 GT-07.5 M1.2 M2.2 M3.2 M4.2 MP1584EN.0
copper on no net:
  other v1: 85.852,75.057 87.249,75.057 85.852,76.2 87.249,76.2 85.852,77.343 87.249,77.343 53.086,89.535 54.102,89.535 55.118,89.535 56.134,89.535 57.15,89.535 58.166,89.535 53.086,90.551 54.102,90.551 55.118,90.551 56.134,90.551 57.15,90.551 58.166,90.551
  other v2: 51.054,35.378 44.554,39.878

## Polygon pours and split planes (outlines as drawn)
GND on Top Layer "Top Layer-No Net" (solid, remove dead copper, pour order 18): 19.685,102.87 113.919,102.87 115.316,101.473 108.458,94.615 108.458,19.685 10.033,19.685 9.906,19.558
GND on Bottom Layer "Top Layer-No Net" (solid, remove dead copper, pour order 20): 21.717,102.997 21.844,102.87 121.031,102.87 121.031,26.162 113.792,18.923 111.252,21.463 21.59,21.463

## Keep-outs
Keep-Out Layer:
  lines w0.254: 26.975,100 103.073,100 cw(c103.073,98.073) 105,98.073 105,27.276 cw(c102.724,27.276) 102.724,25 27.197,25 cw(c27.197,27.197) 25,27.197 25,97.981 cw(c27.126,97.882) 26.975,100.004

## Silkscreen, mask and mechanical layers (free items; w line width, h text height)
Top Overlay:
  text "GND" at 30.099,91.059 h1
  text "PWN" at 35.306,91.059 h1
  text "GND" at 91.694,91.059 h1
  text "PWN" at 96.901,91.059 h1
  text "+" at 59.309,87.503 h1.52 r270
  text "+" at 50.165,86.233 h1.52
  text "3V3" at 96.52,74.803 h1
  text "GND" at 96.52,72.263 h1
  text "SDA" at 30.099,71.628 h1
  text "RX" at 97.536,69.723 h1
  text "SCL" at 30.226,68.961 h1
  text "TX" at 97.536,67.183 h1
  text "GND" at 30.226,66.421 h1
  text "IO" at 84.074,65.532 h1 r90
  text "CLK" at 81.534,64.389 h1 r90
  text "GND" at 86.614,64.389 h1 r90
  text "3V3" at 89.281,64.389 h1 r90
  text "3V3" at 30.226,63.754 h1
  text "3V3" at 30.099,52.832 h1
  text "GND" at 30.099,50.292 h1
  text "3V3" at 96.774,49.022 h1
  text "TX" at 30.099,47.752 h1
  text "GND" at 96.774,46.609 h1
  text "RX" at 30.099,45.212 h1
  text "SCL" at 96.774,44.196 h1
  text "PPS" at 30.099,42.672 h1
  text "SDA" at 96.774,41.656 h1
  text "PWN" at 30.226,33.147 h1
  text "GND" at 35.306,33.147 h1
  text "PWN" at 91.821,32.893 h1
  text "GND" at 96.774,32.893 h1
